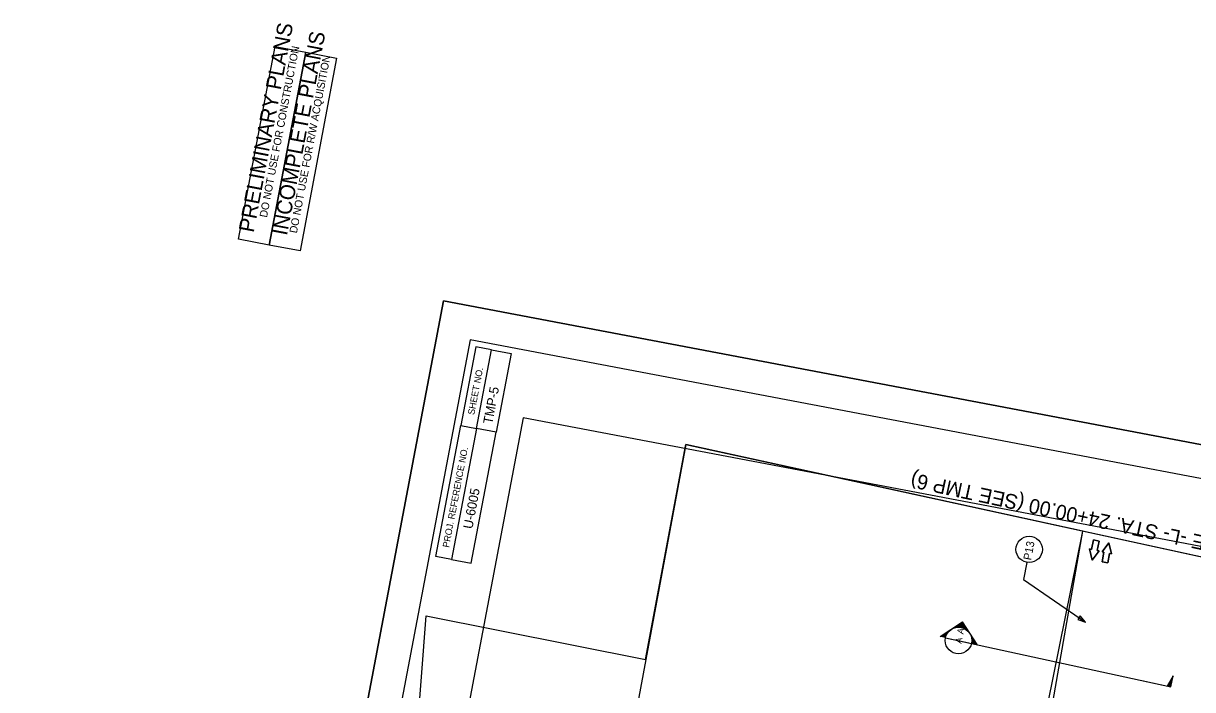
# Model space of a CAD drawing. Extents: x 1615680 to 1617075, y 898420 to 901376.
# Drawn here: x 1615680 to 1616556, y 900877 to 901376 of the extents above; entities that cross this region are included whole.
import ezdxf

# ---------------------------------------------------------------- set-up
doc = ezdxf.new("R2010")
doc.units = 0
for name, color, linetype in [('Default', 7, 'Continuous'), ('DEV BORDER CELL', 7, 'Continuous'), ('DEV DIRECTION OF TRAFFIC FLOW ARROW CELL', 7, 'Continuous'), ('Matchline', 7, 'Continuous'), ('Matchline Text', 7, 'Continuous'), ('Scratch_Level_0', 7, 'Continuous'), ('Sheet Clip Boundary CELL', 7, 'Continuous'), ('Sheet Plot Border Outside CELL', 7, 'Continuous'), ('Sheet Sticker Incomplete CELL', 7, 'Continuous'), ('Sheet Sticker Preliminary CELL', 7, 'Continuous')]:
    doc.layers.add(name, color=color, linetype=linetype)

msp = doc.modelspace()

# ---------------------------------------------------------------- linework, layer by layer
at = {"layer": 'Default'}
for p, q in [((1616366.8, 900916.91), (1616383.64, 900927.73)), ((1616383.48, 900927.57), (1616382.65, 900923.75)), ((1616394.5, 900910.82), (1616383.64, 900927.73)), ((1616369.8, 900918.8), (1616369.27, 900916.37)), ((1616370.05, 900918.96), (1616369.48, 900916.33)), ((1616370.3, 900919.12), (1616369.68, 900916.28)), ((1616370.55, 900919.28), (1616369.88, 900916.24)), ((1616370.79, 900919.44), (1616370.09, 900916.19)), ((1616371.04, 900919.6), (1616370.29, 900916.15)), ((1616371.29, 900919.76), (1616370.49, 900916.11)), ((1616371.54, 900919.92), (1616370.7, 900916.06)), ((1616371.79, 900920.08), (1616371.25, 900917.61)), ((1616372.03, 900920.24), (1616371.68, 900918.61)), ((1616372.28, 900920.4), (1616372.01, 900919.16)), ((1616372.53, 900920.57), (1616372.32, 900919.6)), ((1616372.78, 900920.73), (1616372.63, 900920.03)), ((1616373.03, 900920.89), (1616372.92, 900920.37)), ((1616373.28, 900921.05), (1616373.19, 900920.66)), ((1616373.52, 900921.21), (1616373.47, 900920.95)), ((1616377.28, 900923.59), (1616377.24, 900923.4)), ((1616377.53, 900923.75), (1616377.48, 900923.51)), ((1616377.78, 900923.91), (1616377.72, 900923.62)), ((1616378.03, 900924.07), (1616377.94, 900923.69)), ((1616378.27, 900924.23), (1616378.17, 900923.73)), ((1616378.52, 900924.39), (1616378.39, 900923.77)), ((1616378.77, 900924.54), (1616378.61, 900923.82)), ((1616379.02, 900924.7), (1616378.83, 900923.86)), ((1616379.26, 900924.86), (1616379.06, 900923.91)), ((1616379.51, 900925.02), (1616379.27, 900923.91)), ((1616379.76, 900925.18), (1616379.48, 900923.91)), ((1616380.01, 900925.34), (1616379.7, 900923.91)), ((1616380.26, 900925.5), (1616379.91, 900923.91)), ((1616380.5, 900925.66), (1616380.12, 900923.91)), ((1616380.75, 900925.82), (1616380.34, 900923.91)), ((1616381, 900925.98), (1616380.55, 900923.91)), ((1616381.25, 900926.14), (1616380.76, 900923.91)), ((1616381.5, 900926.29), (1616380.98, 900923.91)), ((1616381.74, 900926.45), (1616381.19, 900923.91)), ((1616381.99, 900926.61), (1616381.4, 900923.89)), ((1616382.24, 900926.77), (1616381.61, 900923.87)), ((1616382.49, 900926.93), (1616381.81, 900923.85)), ((1616382.73, 900927.09), (1616382.02, 900923.82)), ((1616382.98, 900927.25), (1616382.23, 900923.8)), ((1616383.23, 900927.41), (1616382.44, 900923.77)), ((1616383.68, 900927.52), (1616382.85, 900923.72)), ((1616383.84, 900927.27), (1616383.06, 900923.68)), ((1616384, 900927.03), (1616383.26, 900923.63)), ((1616384.16, 900926.78), (1616383.46, 900923.59)), ((1616384.32, 900926.53), (1616383.67, 900923.54)), ((1616384.48, 900926.29), (1616383.87, 900923.5)), ((1616384.64, 900926.04), (1616384.07, 900923.46)), ((1616384.8, 900925.8), (1616384.25, 900923.29)), ((1616384.96, 900925.55), (1616384.44, 900923.17)), ((1616385.12, 900925.3), (1616384.63, 900923.07)), ((1616385.28, 900925.06), (1616384.82, 900922.97)), ((1616385.44, 900924.81), (1616385.01, 900922.88)), ((1616385.6, 900924.57), (1616385.21, 900922.78)), ((1616385.76, 900924.32), (1616385.4, 900922.68)), ((1616385.91, 900924.07), (1616385.59, 900922.58)), ((1616386.07, 900923.83), (1616385.78, 900922.47)), ((1616386.23, 900923.58), (1616385.96, 900922.33)), ((1616386.39, 900923.34), (1616386.14, 900922.19)), ((1616386.55, 900923.09), (1616386.33, 900922.05)), ((1616386.71, 900922.84), (1616386.51, 900921.91)), ((1616386.87, 900922.6), (1616386.69, 900921.77)), ((1616387.03, 900922.35), (1616386.88, 900921.63)), ((1616387.19, 900922.11), (1616387.06, 900921.49)), ((1616387.35, 900921.86), (1616387.24, 900921.35)), ((1616387.51, 900921.61), (1616387.42, 900921.2)), ((1616387.67, 900921.37), (1616387.6, 900921.06)), ((1616387.83, 900921.12), (1616387.78, 900920.91)), ((1616367.07, 900917.03), (1616367.03, 900916.86)), ((1616367.32, 900917.19), (1616367.24, 900916.81)), ((1616367.57, 900917.35), (1616367.44, 900916.77)), ((1616367.82, 900917.51), (1616367.64, 900916.73)), ((1616368.06, 900917.67), (1616367.85, 900916.68)), ((1616368.31, 900917.83), (1616368.05, 900916.64)), ((1616368.56, 900917.99), (1616368.26, 900916.59)), ((1616368.81, 900918.15), (1616368.46, 900916.55)), ((1616369.06, 900918.31), (1616368.66, 900916.5)), ((1616369.3, 900918.48), (1616368.87, 900916.46)), ((1616369.55, 900918.64), (1616369.07, 900916.42)), ((1616370.8, 900915.99), (1616390.34, 900911.73)), ((1616370.8, 900915.98), (1616388.4, 900912.15)), ((1616390.15, 900917.42), (1616390.1, 900917.18)), ((1616390.31, 900917.17), (1616390.24, 900916.84)), ((1616390.34, 900911.73), (1616539.62, 900879.2)), ((1616390.47, 900916.92), (1616390.36, 900916.43)), ((1616390.63, 900916.68), (1616390.49, 900916.02)), ((1616390.79, 900916.43), (1616390.59, 900915.51)), ((1616391.42, 900915.43), (1616390.62, 900911.75)), ((1616391.27, 900915.68), (1616390.68, 900912.97)), ((1616390.95, 900916.18), (1616390.69, 900914.97)), ((1616391.11, 900915.93), (1616390.78, 900914.43)), ((1616391.58, 900915.18), (1616390.83, 900911.7)), ((1616391.74, 900914.93), (1616391.03, 900911.65)), ((1616391.9, 900914.68), (1616391.23, 900911.61)), ((1616392.06, 900914.43), (1616391.43, 900911.56)), ((1616392.22, 900914.18), (1616391.64, 900911.51)), ((1616392.38, 900913.93), (1616391.84, 900911.46)), ((1616392.54, 900913.68), (1616392.04, 900911.42)), ((1616392.69, 900913.43), (1616392.25, 900911.37)), ((1616392.85, 900913.18), (1616392.45, 900911.32)), ((1616393.01, 900912.93), (1616392.65, 900911.28)), ((1616393.17, 900912.69), (1616392.85, 900911.23)), ((1616393.33, 900912.44), (1616393.06, 900911.18)), ((1616393.49, 900912.19), (1616393.26, 900911.14)), ((1616393.65, 900911.94), (1616393.46, 900911.09)), ((1616393.81, 900911.69), (1616393.67, 900911.04)), ((1616393.97, 900911.44), (1616393.87, 900910.99)), ((1616394.12, 900911.19), (1616394.07, 900910.95)), ((1616517.94, 900883.93), (1616539.62, 900879.2)), ((1616541.43, 900887.52), (1616536.99, 900879.78)), ((1616540.56, 900883.55), (1616539.37, 900883.81)), ((1616540.6, 900883.76), (1616539.48, 900884)), ((1616540.64, 900883.96), (1616539.59, 900884.19)), ((1616539.62, 900879.2), (1616541.43, 900887.52)), ((1616540.69, 900884.16), (1616539.7, 900884.38)), ((1616540.73, 900884.37), (1616539.81, 900884.57)), ((1616540.78, 900884.57), (1616539.91, 900884.76)), ((1616540.82, 900884.77), (1616540.02, 900884.95)), ((1616540.87, 900884.98), (1616540.13, 900885.14)), ((1616540.91, 900885.18), (1616540.24, 900885.33)), ((1616540.95, 900885.38), (1616540.35, 900885.52)), ((1616541, 900885.59), (1616540.45, 900885.71)), ((1616541.04, 900885.79), (1616540.56, 900885.9)), ((1616541.09, 900885.99), (1616540.67, 900886.09)), ((1616541.13, 900886.2), (1616540.78, 900886.27)), ((1616541.18, 900886.4), (1616540.89, 900886.46)), ((1616541.22, 900886.61), (1616541, 900886.65)), ((1616541.26, 900886.81), (1616541.1, 900886.84)), ((1616541.31, 900887.01), (1616541.21, 900887.03)), ((1616539.62, 900879.28), (1616537.1, 900879.83)), ((1616539.67, 900879.48), (1616537.21, 900880.02)), ((1616539.71, 900879.69), (1616537.31, 900880.21)), ((1616539.76, 900879.89), (1616537.42, 900880.4)), ((1616539.8, 900880.09), (1616537.53, 900880.59)), ((1616539.85, 900880.3), (1616537.64, 900880.78)), ((1616539.89, 900880.5), (1616537.75, 900880.97)), ((1616539.93, 900880.7), (1616537.86, 900881.16)), ((1616539.98, 900880.91), (1616537.96, 900881.35)), ((1616540.02, 900881.11), (1616538.07, 900881.54)), ((1616540.07, 900881.31), (1616538.18, 900881.72)), ((1616540.11, 900881.52), (1616538.29, 900881.91)), ((1616540.16, 900881.72), (1616538.4, 900882.1)), ((1616540.2, 900881.92), (1616538.51, 900882.29)), ((1616540.24, 900882.13), (1616538.61, 900882.48)), ((1616540.29, 900882.33), (1616538.72, 900882.67)), ((1616540.33, 900882.53), (1616538.83, 900882.86)), ((1616540.38, 900882.74), (1616538.94, 900883.05)), ((1616540.42, 900882.94), (1616539.05, 900883.24)), ((1616540.47, 900883.14), (1616539.16, 900883.43)), ((1616540.51, 900883.35), (1616539.26, 900883.62))]:
    msp.add_line(p, q, dxfattribs=at)
msp.add_lwpolyline([(1616431.72, 900972.41), (1616429.26, 900959.47), (1616475.66, 900927.7)], dxfattribs=at)
msp.add_lwpolyline([(1616470, 900929.69), (1616475.66, 900927.7), (1616471.75, 900932.26)], close=True, dxfattribs=at)
for centre, radius in [((1616433.56, 900982.13), 9.89), ((1616380.57, 900913.86), 10)]:
    msp.add_circle(centre, radius, dxfattribs=at)
at = {"layer": 'DEV BORDER CELL'}
msp.add_line((1616019.39, 901072.79), (1616030.58, 901131.73), dxfattribs=at)
for points in [[(1616014.55, 901139.21), (1615734.74, 899665.53), (1616766.32, 899469.67), (1617046.12, 900943.35)], [(1616019.39, 901072.79), (1616030.58, 901131.73), (1616018.79, 901133.97), (1616007.6, 901075.03)], [(1616019.39, 901072.79), (1616030.58, 901131.73), (1616045.31, 901128.94), (1616034.12, 901069.99)], [(1615988.94, 900976.78), (1616007.6, 901075.03), (1616019.39, 901072.79), (1616000.73, 900974.54)], [(1616019.39, 901072.79), (1616000.73, 900974.54), (1616015.47, 900971.74), (1616034.12, 901069.99)]]:
    msp.add_lwpolyline(points, close=True, dxfattribs=at)
at = {"layer": 'DEV DIRECTION OF TRAFFIC FLOW ARROW CELL'}
for p, q in [((1616481.81, 900989.19), (1616480.32, 900982.15)), ((1616480.32, 900982.15), (1616481.81, 900989.19)), ((1616486.06, 900988.29), (1616481.81, 900989.19)), ((1616481.81, 900989.19), (1616486.06, 900988.29)), ((1616480.32, 900982.15), (1616478.88, 900982.45)), ((1616478.88, 900982.45), (1616480.85, 900974.11)), ((1616480.85, 900974.11), (1616478.88, 900982.45)), ((1616478.88, 900982.45), (1616480.32, 900982.15)), ((1616480.85, 900974.11), (1616486.02, 900980.94)), ((1616486.02, 900980.94), (1616480.85, 900974.11)), ((1616484.58, 900981.25), (1616486.06, 900988.29)), ((1616486.06, 900988.29), (1616484.58, 900981.25)), ((1616486.02, 900980.94), (1616484.58, 900981.25)), ((1616484.58, 900981.25), (1616486.02, 900980.94)), ((1616493.35, 900987.09), (1616488.18, 900980.26)), ((1616488.18, 900980.26), (1616493.35, 900987.09)), ((1616488.18, 900980.26), (1616489.63, 900979.96)), ((1616489.63, 900979.96), (1616488.18, 900980.26)), ((1616495.32, 900978.75), (1616493.35, 900987.09)), ((1616493.35, 900987.09), (1616495.32, 900978.75)), ((1616489.63, 900979.96), (1616488.14, 900972.91)), ((1616488.14, 900972.91), (1616489.63, 900979.96)), ((1616488.14, 900972.91), (1616492.39, 900972.01)), ((1616492.39, 900972.01), (1616488.14, 900972.91)), ((1616492.39, 900972.01), (1616493.88, 900979.06)), ((1616493.88, 900979.06), (1616492.39, 900972.01)), ((1616493.88, 900979.06), (1616495.32, 900978.75)), ((1616495.32, 900978.75), (1616493.88, 900979.06))]:
    msp.add_line(p, q, dxfattribs=at)
at = {"layer": 'Matchline'}
msp.add_line((1616176.29, 901060.7), (1616775.18, 900930.23), dxfattribs=at)
at = {"layer": 'Scratch_Level_0'}
for points in [[(1616054.34, 901080.76), (1615793.19, 899705.33), (1616726.52, 899528.12), (1616890.46, 900391.55), (1616774.26, 900413.61), (1616871.48, 900925.61)], [(1616209.3, 899662.81), (1616429.94, 900746.4), (1616473.81, 900995.89), (1616176.29, 901060.7), (1615925.06, 899711.77)], [(1616209.3, 899662.81), (1616345.54, 900332.12), (1616365.47, 900329.48), (1616372.31, 900327.99), (1616373.8, 900334.83), (1616366.96, 900336.32), (1616342.58, 900347.76), (1616473.81, 900995.89), (1616176.29, 901060.7), (1615925.06, 899711.77)]]:
    msp.add_lwpolyline(points, close=True, dxfattribs=at)
at = {"layer": 'Sheet Clip Boundary CELL'}
msp.add_lwpolyline([(1616176.29, 901060.7), (1616913.78, 900900.04), (1616896.28, 900812.91), (1616872.94, 900688.21), (1616835.87, 900695.21), (1616753.94, 900262.18), (1616898.09, 900233.43), (1616663.91, 899565.73), (1616252.62, 899604.04), (1615894.68, 899796.73), (1615981.58, 900932.46), (1616145.94, 900899.57)], close=True, dxfattribs=at)
at = {"layer": 'Sheet Plot Border Outside CELL'}
for points in [[(1616760.47, 899304.87), (1615679.78, 899510.06), (1615994.65, 901168.43), (1617075.34, 900963.24)], [(1616760.47, 899304.87), (1617075.34, 900963.24), (1615994.65, 901168.43), (1615679.78, 899510.06)]]:
    msp.add_lwpolyline(points, close=True, dxfattribs=at)
at = {"layer": 'Sheet Sticker Incomplete CELL'}
msp.add_lwpolyline([(1615887.11, 901205.77), (1615864.02, 901210.16), (1615891.44, 901354.58), (1615914.53, 901350.19)], close=True, dxfattribs=at)
at = {"layer": 'Sheet Sticker Preliminary CELL'}
msp.add_lwpolyline([(1615864.02, 901210.16), (1615840.93, 901214.54), (1615868.36, 901358.96), (1615891.44, 901354.58)], close=True, dxfattribs=at)

# ---------------------------------------------------------------- texts
at = {"layer": 'Default'}
for s, height, rotation, p in [('P13', 6, 79.24933, (1616435, 900973.65)), ('A', 5, 77.71319, (1616384.26, 900918.24)), ('A', 5, 77.71319, (1616382.74, 900911.25))]:
    msp.add_text(s, height=height, rotation=rotation, dxfattribs=at).set_placement(p)
at = {"layer": 'DEV BORDER CELL'}
for s, height, rotation, p in [('SHEET NO.', 4.999, 79.24992, (1616017.69, 901082.61)), ('TMP-5', 7, 79.24937, (1616031.12, 901075.64)), ('PROJ. REFERENCE NO.', 4.9992, 79.24992, (1615998.81, 900983.16)), ('U-6005', 7, 79.24937, (1616016.2, 900997.05))]:
    msp.add_text(s, height=height, rotation=rotation, dxfattribs=at).set_placement(p)
at = {"layer": 'Matchline Text'}
msp.add_text('MATCHLINE -L- STA. 24+00.00 (SEE TMP 6)', height=11, rotation=167.79564, dxfattribs=at).set_placement((1616639.68, 900976.22))
at = {"layer": 'Sheet Sticker Incomplete CELL'}
for s, height, p in [('INCOMPLETE PLANS', 11.52, (1615877.28, 901216.75)), ('DO NOT USE FOR R/W ACQUISITION', 5.76, (1615884.72, 901218.65))]:
    msp.add_text(s, height=height, rotation=79.24937, dxfattribs=at).set_placement(p)
at = {"layer": 'Sheet Sticker Preliminary CELL'}
for s, height, p in [('PRELIMINARY PLANS', 11.52, (1615852.32, 901219)), ('DO NOT USE FOR CONSTRUCTION', 5.76, (1615862.32, 901230.43))]:
    msp.add_text(s, height=height, rotation=79.24937, dxfattribs=at).set_placement(p)

doc.saveas('drawing.dxf')
